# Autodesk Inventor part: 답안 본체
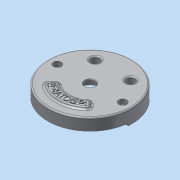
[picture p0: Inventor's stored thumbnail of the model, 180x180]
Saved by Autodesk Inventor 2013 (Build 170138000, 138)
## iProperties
Created: 2015-04
Part Number: 답안 본체
Material: 알루미늄 6061
Document SubType Name: Modeling
Designer: Administrator
Density: 2.71 g/cm^3
Mass: 1268.25 g
Surface Area: 1022 cm^2
Volume: 467.99 cm^3
Author: Administrator
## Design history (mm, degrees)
sketch "스케치1"
  geometry: C1 r 95 at (0, 0); 1 further point
  constraints: 1 centre point, 1 coincident
  dimensions: "d0" = 190 diameter of C1
extrude "돌출1" new body sketch "스케치1" stored distance "d1" = 32; taper "d2" = 0 deg
sketch "스케치2"
  geometry: C1 r 95 at (0, 0) reference; C2 r 90 at (0, 0)
  constraints: 1 centre point, 1 coincident
  dimensions: "d4" = 180 diameter of C2
extrude "돌출2" cut sketch "스케치2" distance "d5" = 21; taper "d6" = 0 deg
sketch "스케치3"
  geometry: L1 (0, 0)-(95, 0); L2 (0, 0)-(0, 95); L3 (0, 0)-(-95, 0); L4 (89.658, -7.844)-(94.638, -8.28); L5 (-89.658, -7.844)-(-94.638, -8.28); A1 r 95 centre (0, 0) between (0, 95) and (95, 0) reference; A2 r 90 centre (0, 0) between (-89.658, -7.844) and (89.658, -7.844); A3 r 95 centre (0, 0) between (-94.638, -8.28) and (94.638, -8.28); 1 further point
  constraints: 10 end point, 8 point on circle, 3 coincident, 2 centre point, 2 perpendicular, 2 symmetric about line, 1 concentric, 1 horizontal, 2 other
  dimensions: "d97" = 5 deg dimension on point (0, 0) L1.end L4.start; "d98" = 5 deg dimension on point (0, 0) L1.end L4.end
extrude "돌출3" cut sketch "스케치3" distance "d12" = 5; taper "d13" = 0 deg
sketch "스케치4"
  geometry: L1 (-89.196, 12)-(-40.249, 12); L2 (40.249, 12)-(89.196, 12); A1 r 90 centre (0, 0) between (-89.196, 12) and (89.196, 12) reference; A2 r 42 centre (0, 0) between (40.249, 12) and (-40.249, 12)
  constraints: 4 end point, 4 point on circle, 2 horizontal, 1 centre point, 1 coincident, 1 collinear
  dimensions: "d14" = 84 diameter of A2; "d16" = 12 distance from line of A1.centre L2
extrude "돌출4" join sketch "스케치4" stored distance "d17" = 5; taper "d18" = 0 deg
sketch "스케치19"
  geometry: L1 (-94.638, -8.28)-(-89.658, -7.844) reference; L2 (-89.196, 12)-(-40.249, 12) reference; L3 (40.249, 12)-(89.196, 12) reference; L4 (89.658, -7.844)-(94.638, -8.28) reference; L5 (-40.249, 12)-(-89.196, 12); L6 (40.249, 12)-(89.196, 12); A1 r 42 centre (0, 0) between (40.249, 12) and (-40.249, 12) reference; A2 r 95 centre (0, 0) between (94.638, -8.28) and (-94.638, -8.28) reference; A3 r 90 centre (0, 0) between (89.196, 12) and (-89.196, 12); A4 r 42 centre (0, 0) between (40.249, 12) and (-40.249, 12)
  constraints: 8 end point, 5 point on circle, 2 centre point, 2 coincident, 2 collinear, 2 point on line, 1 concentric
extrude "돌출18" cut sketch "스케치19" distance "d99" = 25; taper "d100" = 0 deg
sketch "스케치6"
  geometry: C1 r 35 at (0, 0); A1 r 90 centre (0, 0) between (-89.196, 12) and (89.196, 12) reference
  constraints: 1 centre point, 1 coincident
  dimensions: "d21" = 70 diameter of C1
extrude "돌출6" join sketch "스케치6" distance "d22" = 10; taper "d23" = -10 deg
sketch "스케치7"
  geometry: C1 r 33.237 at (0, 0) reference; C2 r 25 at (0, 0)
  constraints: 1 centre point, 1 coincident
  dimensions: "d24" = 50 diameter of C2
extrude "돌출7" cut sketch "스케치7" distance "d25" = 15; taper "d26" = 0 deg
sketch "스케치8"
  geometry: C1 r 25 at (0, 0) reference; C2 r 11.5 at (0, 0)
  constraints: 1 centre point, 1 coincident
  dimensions: "d27" = 23 diameter of C2
extrude "돌출8" cut sketch "스케치8" stored distance "d28" = 15; taper "d29" = 0 deg
sketch "스케치15"
  geometry: C1 r 35 at (0, 0) reference; A1 r 59 centre (0, -19) between (-58.704, -13.1) and (58.704, -13.1); A2 r 41 centre (0, -19) between (-40.794, -14.9) and (40.794, -14.9); A3 r 9 centre (49.749, -14) between (58.704, -13.1) and (40.794, -14.9); A4 r 9 centre (-49.749, -14) between (-40.794, -14.9) and (-58.704, -13.1)
  constraints: 8 point on circle, 4 centre point, 2 tangent, 1 coincident, 1 horizontal alignment, 1 vertical alignment
  dimensions: "d59" = 118 diameter of A1; "d60" = 19 distance of C1.centre A1.centre; "d61" = 82 diameter of A2; "d62" = 18 diameter of A3; "d63" = 5 vertical distance of A2.centre A3.centre; "d64" = 18 diameter of A4
extrude "돌출15" cut sketch "스케치15" distance "d65" = 7; taper "d66" = 0 deg
fillet "모깎기3" dims "d69" = 1
fillet "모깎기4" dims "d70" = 3
chamfer "모따기1" distance "d72" = 1; stored, may be unused: second distance "d73" = 2, angle "d74" = 45 deg
fillet "모깎기6" dims "d78" = 3
sketch "스케치16"
  geometry: L1 (0, 0)-(-50.912, -50.912); L2 (0, 0)-(0, -72); L3 (0, 0)-(50.912, -50.912); L4 (50.912, -50.912)-(36.062, -36.062); L5 (-50.912, -50.912)-(-36.062, -36.062); C1 r 12.5 at (0, 0) reference; A1 r 72 centre (0, 0) between (-50.912, -50.912) and (50.912, -50.912); A2 r 51 centre (0, 0) between (-36.062, -36.062) and (36.062, -36.062)
  constraints: 10 end point, 5 point on circle, 2 centre point, 2 coincident, 2 point on line, 1 vertical
  dimensions: "d81" = 144 diameter of A1; "d82" = 102 diameter of A2; "d83" = 45 deg angle of L1 L2; "d84" = 45 deg angle of L2 L3
extrude "돌출16" join sketch "스케치16" distance "d85" = 5; taper "d86" = 0 deg
sketch "스케치17"
  geometry: C1 r 68 at (0, 0); A1 r 51 centre (0, 0) between (-36.062, -36.062) and (36.062, -36.062) reference
  constraints: 1 centre point, 1 coincident, 1 other
  dimensions: "d87" = 136 diameter of C1
feature "엠보싱1" sketch "스케치17" dims "d0" = 190, "d88" = 0.5, "d89" = 0
fillet "모깎기7" dims "d90" = 5
fillet "모깎기8" dims "d91" = 5
fillet "모깎기9" dims "d92" = 3
sketch "스케치20"
  geometry: C1 r 15 at (40, 52); C2 r 15 at (-40, 52); A1 r 42 centre (0, 0) between (40.249, 12) and (-40.249, 12) reference
  constraints: 2 centre point
  dimensions: "d101" = 30 diameter of C1; "d103" = 52 vertical distance of A1.centre C1.centre; "d104" = 40 horizontal distance of C1.centre A1.centre; "d105" = 30 diameter of C2; "d106" = 40 horizontal distance of A1.centre C2.centre; "d107" = 52 vertical distance of A1.centre C2.centre
extrude "돌출19" join sketch "스케치20" stored distance "d108" = 25; taper "d109" = 0 deg
sketch "스케치21"
  geometry: C1 r 15 at (0, 0) reference; C2 r 10 at (0, 0); C3 r 15 at (80, 0) reference; C4 r 10 at (80, 0); 1 further point
  constraints: 2 centre point, 2 coincident
  dimensions: "d110" = 20 diameter of C2; "d111" = 20 diameter of C4
extrude "돌출20" cut sketch "스케치21" stored distance "d112" = 25; taper "d113" = 0 deg
sketch "스케치22"
  geometry: L1 (13.748, 6)-(-13.748, 6); L2 (-13.748, -6)-(13.748, -6); L3 (66.252, 6)-(93.748, 6); L4 (93.748, -6)-(66.252, -6); C1 r 10 at (0, 0) reference; C2 r 10 at (80, 0) reference; A1 r 15 centre (0, 0) between (13.748, 6) and (-13.748, 6) reference; A2 r 15 centre (80, 0) between (66.252, 6) and (93.748, 6) reference; 1 further point
  constraints: 8 end point, 8 point on circle, 3 parallel, 1 horizontal
  dimensions: "d115" = 6 distance from line of L1 C1.centre; "d116" = 6 distance from line of L2 C1.centre; "d117" = 6 distance from line of L4 C2.centre; "d118" = 6 distance from line of C2.centre L3
extrude "돌출21" cut sketch "스케치22" distance "d119" = 3; taper "d120" = 0 deg
sketch "스케치24"
  geometry: L1 (-6, 13.748)-(-6, -13.748); L2 (6, -13.748)-(6, 13.748); C1 r 10 at (0, 0) reference; A1 r 15 centre (0, 0) between (-6, 13.748) and (-6, -13.748) reference; 1 further point
  constraints: 4 end point, 4 point on circle, 1 parallel, 1 vertical
  dimensions: "d122" = 6 distance from line of C1.centre L1; "d123" = 6 distance from line of L2 C1.centre
extrude "돌출22" cut sketch "스케치24" distance "d124" = 3; taper "d125" = 0 deg
fillet "모깎기10" dims "d126" = 3
fillet "모깎기11" dims "d127" = 10
fillet "모깎기12" dims "d128" = 3
fillet "모깎기13" dims "d129" = 3
fillet "모깎기14" dims "d130" = 0.3
sketch "스케치25"
  geometry: C1 r 35 at (0, 0) reference; C2 r 9 at (74, 0); C3 r 9 at (-74, 0); A1 r 87 centre (0, 0) between (-85.385, 16.684) and (85.385, 16.684) reference; A2 r 74 centre (0, 0) between (74, 0) and (-74, 0)
  constraints: 3 centre point, 2 horizontal alignment, 2 point on circle, 1 coincident
  dimensions: "d131" = 148 diameter of A2; "d132" = 18 diameter of C2; "d133" = 18 diameter of C3
extrude "돌출23" join sketch "스케치25" stored distance "d134" = 11; taper "d135" = 0 deg
sketch "스케치26"
  geometry: L1 (-42.975, -35.904)-(-50.78, -43.709) reference; L2 (50.78, -43.709)-(42.975, -35.904) reference; C1 r 9 at (74, 0) reference; C2 r 13 at (-40, 52) reference; C3 r 12.5 at (0, 0) reference; C4 r 92 at (0, 0) reference; C5 r 13 at (40, 52) reference; C6 r 9 at (-74, 0) reference; A1 r 10 centre (-35.904, -42.975) between (-29.493, -35.301) and (-42.975, -35.904) reference; A2 r 46 centre (0, 0) between (-29.493, -35.301) and (29.493, -35.301) reference; A3 r 10 centre (35.904, -42.975) between (42.975, -35.904) and (29.493, -35.301) reference; A4 r 10 centre (43.709, -50.78) between (50.232, -58.359) and (50.78, -43.709) reference; A5 r 77 centre (0, 0) between (-50.232, -58.359) and (50.232, -58.359) reference; A6 r 10 centre (-43.709, -50.78) between (-50.78, -43.709) and (-50.232, -58.359) reference; 2 further points
  constraints: 2 coincident
hole "구멍1" sketch "스케치26" at (-74, 0), (74, 0) diameter "d136" = 11; stored, may be unused: countersink angle "d140" = 90 deg, drill point angle "d142" = 118 deg; dims "d137" = 6, "d138" = 18, "d139" = 11, "d141" = 8
fillet "모깎기15" dims "d143" = 3
node "솔리드1"
node "투영된 루프3"
node "투영된 루프4"
node "투영된 루프5"
other parameters: "d15" = 12
